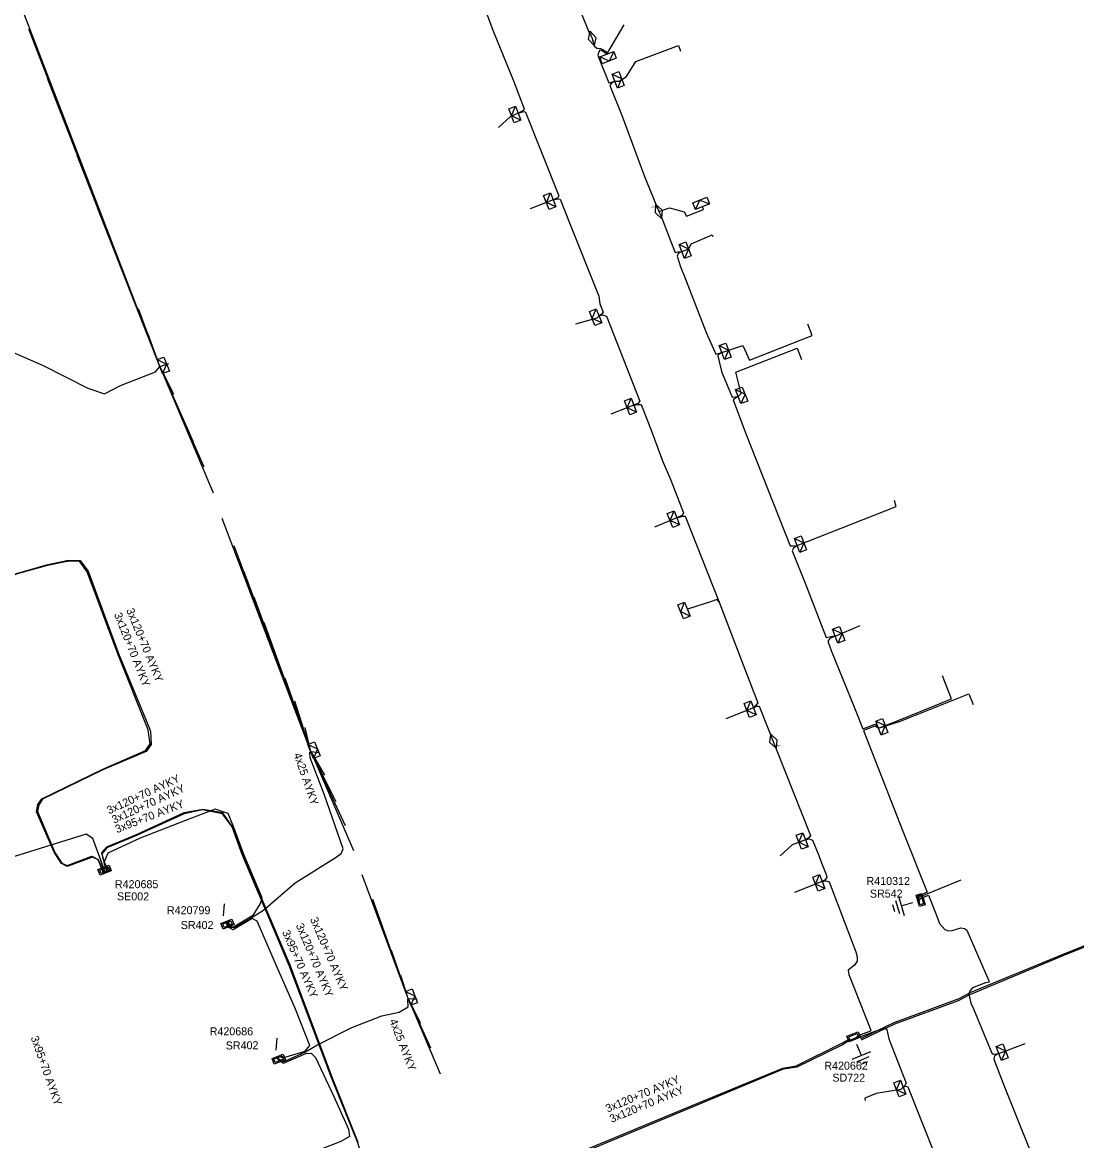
# Model space of a CAD drawing. Extents: x -540028 to -538776, y -1157064 to -1155670.
# Drawn here: x -539818.5 to -539686.8, y -1156318.7 to -1156179 of the extents above; entities that cross this region are included whole.
import ezdxf

# ---------------------------------------------------------------- set-up
doc = ezdxf.new("R2010")
doc.units = 0
for name, color, linetype in [('Vrstva 15', 7, 'Continuous'), ('Vrstva 19', 7, 'Continuous'), ('Vrstva 2', 7, 'Continuous'), ('Vrstva 28', 7, 'Continuous'), ('Vrstva 29', 7, 'Continuous'), ('Vrstva 30', 7, 'Continuous'), ('Vrstva 31', 7, 'Continuous'), ('Vrstva 5', 7, 'Continuous'), ('Vrstva 52', 7, 'Continuous'), ('Vrstva 59', 7, 'Continuous'), ('Vrstva 6', 7, 'Continuous')]:
    doc.layers.add(name, color=color, linetype=linetype)

# ---------------------------------------------------------------- blocks, each defined once
blk = doc.blocks.new('17')
at = {"layer": 'Vrstva 2'}
blk.add_lwpolyline([(-1.875, 0), (0, 0.9375), (1.875, 0), (0, -0.9375)], close=True, dxfattribs=at)
blk = doc.blocks.new('17.1')
at = {"layer": 'Vrstva 2'}
blk.add_lwpolyline([(-1.875, 0), (0, 0.9375), (1.875, 0), (0, -0.9375)], close=True, dxfattribs=at)
blk.add_text('T', height=0.75, dxfattribs=at).set_placement((-1.875, -1.35))
blk = doc.blocks.new('132')
at = {"layer": 'Vrstva 2'}
for points in [[(-1.5, 1.5), (1.5, 1.5), (1.5, 0), (-1.5, 0)], [(-1.1, 1.2), (1.1, 1.2), (1.1, 0.3), (-1.1, 0.3)]]:
    blk.add_lwpolyline(points, close=True, dxfattribs=at)
blk = doc.blocks.new('23')
at = {"layer": 'Vrstva 2'}
blk.add_lwpolyline([(1.875, -1.8), (-1.875, -1.8), (-1.875, 0), (1.875, 0)], close=True, dxfattribs=at)
blk.add_lwpolyline([(1.875, 0), (0, -1.8), (-1.875, 0)], dxfattribs=at)
blk = doc.blocks.new('11')
at = {"layer": 'Vrstva 2'}
for p, q in [((0, -4.3), (0, -1.3)), ((-2.5, -4.3), (2.5, -4.3)), ((-1.7, -5.3), (1.7, -5.3)), ((-0.9, -6.3), (0.9, -6.3))]:
    blk.add_line(p, q, dxfattribs=at)

msp = doc.modelspace()

# ---------------------------------------------------------------- linework, layer by layer
at = {"layer": 'Vrstva 5'}
for points in [[(-539754.47, -1156163.05), (-539754.32, -1156163.21), (-539753.53, -1156165.27), (-539752.45, -1156168.17), (-539750.8, -1156172.24), (-539750.34, -1156173.42), (-539748.88, -1156177.28), (-539747.67, -1156180.3), (-539747.55, -1156180.35), (-539747.29, -1156180.99)], [(-539761.06, -1156176.27), (-539759.68, -1156179.97), (-539757.13, -1156186.3), (-539755.77, -1156189.78), (-539755.86, -1156189.98), (-539756.54, -1156190.32), (-539755.83, -1156190.1), (-539755.61, -1156190.2), (-539751.46, -1156200.66), (-539751.58, -1156200.92), (-539752.17, -1156201.15), (-539751.55, -1156201.02), (-539751.27, -1156201.08), (-539750.11, -1156204.01), (-539746.47, -1156213.2), (-539746.33, -1156214.13), (-539745.92, -1156215.19), (-539746.07, -1156215.42), (-539746.43, -1156215.64), (-539746.04, -1156215.53), (-539745.49, -1156215.68), (-539741.31, -1156226.32), (-539741.6, -1156226.6), (-539742.09, -1156226.8), (-539741.55, -1156226.7), (-539741.16, -1156226.71), (-539739.78, -1156230.26), (-539738.5, -1156233.74), (-539737.46, -1156236.16), (-539735.86, -1156240.23), (-539736.01, -1156240.55), (-539736.72, -1156240.88), (-539735.96, -1156240.67), (-539735.67, -1156240.67), (-539731.41, -1156251.42), (-539728.62, -1156258.71), (-539726.57, -1156263.97), (-539726.82, -1156264.29), (-539727.14, -1156264.61), (-539726.79, -1156264.39), (-539726.41, -1156264.39), (-539720.01, -1156280.56), (-539720.23, -1156280.84), (-539720.64, -1156281.08), (-539720.18, -1156280.96), (-539719.76, -1156281.14), (-539718.97, -1156283.04), (-539718.73, -1156283.78), (-539718.04, -1156285.44), (-539717.95, -1156285.8), (-539718.17, -1156286.11), (-539718.56, -1156286.32), (-539718.1, -1156286.22), (-539717.69, -1156286.34), (-539714.34, -1156295.09), (-539714.16, -1156295.71), (-539714.19, -1156296.27), (-539714.51, -1156296.75), (-539715.3, -1156297.4), (-539715.23, -1156297.92), (-539712.47, -1156304.86), (-539712.51, -1156305.01), (-539714.11, -1156305.58), (-539714.39, -1156305.86), (-539714.35, -1156306)], [(-539747.29, -1156180.99), (-539747.03, -1156181.91), (-539746.7, -1156182.22), (-539746.25, -1156182.26), (-539746.04, -1156182.31), (-539745.58, -1156182.62), (-539745.45, -1156182.82), (-539745.47, -1156182.97)], [(-539745.47, -1156182.97), (-539745.61, -1156182.93), (-539745.72, -1156182.76), (-539746.12, -1156182.49), (-539746.32, -1156182.45), (-539746.44, -1156182.65), (-539746.58, -1156183.06), (-539746.49, -1156183.34), (-539745.22, -1156186.53), (-539745, -1156186.48), (-539744.46, -1156186.32), (-539744.92, -1156186.63), (-539745.07, -1156186.85), (-539743.55, -1156190.71), (-539740.75, -1156198.23), (-539738.96, -1156202.6), (-539738.7, -1156203.12), (-539737.44, -1156206.36), (-539736.9, -1156207.71), (-539736.58, -1156207.66), (-539736.1, -1156207.61), (-539736.53, -1156207.86), (-539736.65, -1156208.19), (-539736.26, -1156209.53), (-539735.83, -1156210.52), (-539733.05, -1156217.73), (-539731.84, -1156220.41), (-539731.56, -1156220.34), (-539731.1, -1156220.24), (-539731.53, -1156220.51), (-539731.59, -1156220.64), (-539731.11, -1156222.61), (-539729.78, -1156225.79), (-539729.43, -1156225.78), (-539729.03, -1156225.73), (-539729.36, -1156225.92), (-539729.69, -1156226.15), (-539728.12, -1156230.27), (-539722.53, -1156244.38), (-539722.23, -1156244.39), (-539721.69, -1156244.34), (-539722.12, -1156244.65), (-539722.28, -1156244.98), (-539720.58, -1156249.23), (-539718.04, -1156255.81), (-539717.28, -1156255.66), (-539716.91, -1156255.65), (-539717.61, -1156255.96), (-539717.85, -1156256.3), (-539717.41, -1156257.44), (-539714.53, -1156264.62), (-539713.49, -1156267.24), (-539711.94, -1156266.64), (-539711.53, -1156267.13), (-539711.97, -1156266.91), (-539713.4, -1156267.43), (-539708.49, -1156280), (-539705.43, -1156287.63), (-539706.58, -1156288.13), (-539706.7, -1156288.43)], [(-539826.32, -1156250.92), (-539819.2, -1156247.81), (-539815.3, -1156246.71), (-539812.7, -1156246.18), (-539811.25, -1156246.22), (-539810.27, -1156247.55), (-539806.46, -1156257.83), (-539802.57, -1156267.21), (-539802.46, -1156267.55), (-539802.39, -1156269.2), (-539802.99, -1156270.08), (-539808.42, -1156272.37), (-539815.96, -1156276.02), (-539816.4, -1156276.72), (-539816.57, -1156277.55), (-539814.42, -1156282.68), (-539813.56, -1156284.02), (-539812.88, -1156284.3), (-539809.79, -1156283.14), (-539808.99, -1156283.54), (-539808.71, -1156284.18), (-539808.23, -1156285.27)], [(-539808.35, -1156285.31), (-539808.75, -1156284.2), (-539809.01, -1156283.6), (-539809.72, -1156283.25), (-539812.86, -1156284.41), (-539813.59, -1156284.05), (-539814.52, -1156282.66), (-539816.7, -1156277.62), (-539816.54, -1156276.68), (-539816.05, -1156275.98), (-539808.42, -1156272.29), (-539803.07, -1156269.92), (-539802.5, -1156269.11), (-539802.7, -1156267.67), (-539802.75, -1156267.34), (-539806.55, -1156257.87), (-539810.37, -1156247.64), (-539811.34, -1156246.27), (-539812.66, -1156246.28), (-539815.33, -1156246.82), (-539819.13, -1156247.88), (-539826.28, -1156251.03)], [(-539792.97, -1156291.3), (-539792.59, -1156291.98), (-539792.37, -1156292.02), (-539791.94, -1156292.07), (-539790.05, -1156290.96), (-539789.75, -1156290.75), (-539788.35, -1156289.9), (-539784.4, -1156286.48), (-539779.28, -1156283.25), (-539778.63, -1156282.82), (-539778.4, -1156282.24), (-539780.75, -1156275.4), (-539782.53, -1156270.86), (-539782.56, -1156270.17), (-539782.45, -1156270.07)], [(-539713.64, -1156306.09), (-539709.48, -1156304.1), (-539701.5, -1156301.17), (-539700.17, -1156300.47), (-539688.46, -1156295.54), (-539660.98, -1156284.52), (-539655.52, -1156282.63), (-539647.32, -1156279.46), (-539637.77, -1156275.82)], [(-539776.5, -1156318.89), (-539779.74, -1156310.88), (-539785.02, -1156296.77), (-539790.94, -1156282.9), (-539792.22, -1156279.47), (-539793.43, -1156277.72), (-539795.89, -1156277.32), (-539798.28, -1156277.73), (-539804.24, -1156280.49), (-539807.96, -1156282.01), (-539808.6, -1156282.72), (-539808.19, -1156284.29), (-539807.93, -1156285.15)], [(-539779, -1156347.91), (-539779.95, -1156346.73), (-539779.73, -1156345.88), (-539778.61, -1156344.9), (-539775.24, -1156343.33), (-539770.56, -1156341.04), (-539769.48, -1156340.33), (-539769.63, -1156339.03), (-539771.64, -1156333.68), (-539773.7, -1156328.29), (-539775.54, -1156322.32), (-539776.58, -1156318.93), (-539779.82, -1156310.93), (-539785.14, -1156296.81), (-539791.02, -1156282.92), (-539792.28, -1156279.49), (-539793.49, -1156277.84), (-539795.98, -1156277.37), (-539798.25, -1156277.83), (-539804.23, -1156280.56), (-539807.94, -1156282.09), (-539808.56, -1156282.83), (-539808.18, -1156284.31), (-539807.82, -1156285.1)], [(-539792.85, -1156291.25), (-539792.48, -1156291.89), (-539792.11, -1156291.98), (-539789.61, -1156290.46), (-539788.71, -1156289.04), (-539788.52, -1156288.36), (-539790.8, -1156282.91), (-539792.1, -1156279.43), (-539792.75, -1156277.81), (-539794.39, -1156277.27), (-539798.1, -1156278.69), (-539803.74, -1156280.89), (-539807.78, -1156282.78), (-539808.24, -1156283.84), (-539807.7, -1156285.06)], [(-539713.7, -1156305.93), (-539709.54, -1156303.92), (-539701.45, -1156300.9), (-539700.08, -1156300.16), (-539688.52, -1156295.42), (-539661.09, -1156284.36), (-539655.55, -1156282.49), (-539647.32, -1156279.34), (-539647.14, -1156279.27), (-539646.88, -1156279.78)], [(-539808.1, -1156285.22), (-539809.67, -1156280.95), (-539810.49, -1156280.4), (-539819.47, -1156283.18), (-539829.52, -1156287.35), (-539831.83, -1156288.01), (-539835.74, -1156289.34), (-539852.03, -1156295.75), (-539867.05, -1156301.42), (-539893.47, -1156311.06), (-539905.35, -1156315.36), (-539906.2, -1156315.83), (-539906.45, -1156316.73), (-539906.39, -1156317.1)], [(-539706.55, -1156288.92), (-539706.28, -1156288.43), (-539705.28, -1156287.99), (-539704.31, -1156290.44), (-539703.89, -1156291.54), (-539703.24, -1156292.29), (-539702.77, -1156292.47), (-539702.29, -1156292.44), (-539701.24, -1156292.08), (-539700.76, -1156292.19), (-539700.49, -1156292.38), (-539697.72, -1156298.71), (-539697.69, -1156298.88), (-539698.15, -1156298.95), (-539699.76, -1156299.58), (-539700.08, -1156299.92), (-539700.23, -1156300.35), (-539699.98, -1156301.52), (-539699.63, -1156302.22), (-539697.35, -1156307.75), (-539697.13, -1156307.88), (-539696.47, -1156307.77), (-539697.02, -1156308.09), (-539697.12, -1156308.51), (-539695.93, -1156311.52), (-539690.98, -1156323.89)], [(-539786.41, -1156308.11), (-539785.95, -1156308.31), (-539783.14, -1156307.49), (-539782.54, -1156306.77), (-539784.44, -1156302.04), (-539786.58, -1156297.14), (-539789.15, -1156291.24), (-539789.76, -1156290.91), (-539792.15, -1156292.34), (-539792.68, -1156292.06), (-539793.09, -1156291.34)], [(-539786.58, -1156308.18), (-539786.44, -1156308.48), (-539785.78, -1156308.78), (-539783.08, -1156307.59), (-539781.7, -1156306.73), (-539777.3, -1156304.53), (-539773.58, -1156303.08), (-539771.41, -1156302.61), (-539770.27, -1156301.95), (-539770.32, -1156301.04), (-539770.27, -1156300.9)], [(-539714.18, -1156305.93), (-539714.19, -1156305.89), (-539714.05, -1156305.77), (-539711.92, -1156305.02), (-539710.74, -1156304.57), (-539710.49, -1156304.79), (-539710.22, -1156305.95), (-539708.05, -1156311.49), (-539708.21, -1156311.78), (-539708.42, -1156312), (-539708.14, -1156311.87), (-539707.85, -1156311.96), (-539702.63, -1156325.04)], [(-539779.43, -1156348.07), (-539780.03, -1156346.76), (-539779.79, -1156345.7), (-539778.81, -1156344.68), (-539775.19, -1156343.16), (-539770.61, -1156340.97), (-539769.67, -1156340.19), (-539769.72, -1156339.08), (-539771.9, -1156333.83), (-539772.63, -1156331.81), (-539772.46, -1156331.12), (-539768.16, -1156328.91), (-539760.28, -1156325.42), (-539754.68, -1156322.8), (-539751.87, -1156321.38), (-539734.78, -1156314.29), (-539723.45, -1156309.64), (-539721.79, -1156309.32), (-539716.19, -1156306.53), (-539715.16, -1156306), (-539714.89, -1156306.22)], [(-539779.1, -1156347.94), (-539779.99, -1156346.75), (-539779.78, -1156345.83), (-539778.71, -1156344.76), (-539775.28, -1156343.26), (-539770.58, -1156340.98), (-539769.62, -1156340.26), (-539769.67, -1156339.06), (-539771.71, -1156333.71), (-539772.29, -1156331.91), (-539772.31, -1156331.17), (-539768.05, -1156329.1), (-539760.25, -1156325.54), (-539754.53, -1156322.92), (-539751.76, -1156321.51), (-539734.73, -1156314.46), (-539723.4, -1156309.72), (-539721.66, -1156309.44), (-539716.13, -1156306.73), (-539715.24, -1156306.18), (-539715.07, -1156306.3)], [(-539786.69, -1156308.23), (-539786.54, -1156308.51), (-539785.86, -1156308.98), (-539783.04, -1156307.79), (-539782.4, -1156307.75), (-539781.84, -1156308.29), (-539779.58, -1156313.15), (-539777.72, -1156317.26), (-539777.6, -1156318.14), (-539778.7, -1156318.77), (-539784.02, -1156320.88), (-539795.1, -1156324.88), (-539804.64, -1156328.28), (-539811.88, -1156330.75), (-539813.44, -1156331.06), (-539814.03, -1156330.55), (-539816.6, -1156323.5), (-539818.29, -1156320), (-539820, -1156320.5)]]:
    msp.add_lwpolyline(points, dxfattribs=at)
at = {"layer": 'Vrstva 52'}
for points in [[(-539744.46, -1156186.32), (-539743.91, -1156186.32), (-539742.98, -1156185.76), (-539741.82, -1156183.89), (-539736.5, -1156181.87), (-539736.23, -1156182.56)], [(-539756.54, -1156190.32), (-539757.55, -1156190.79), (-539758.97, -1156192.12)], [(-539752.17, -1156201.15), (-539755.03, -1156202.28)], [(-539738.96, -1156202.6), (-539737.62, -1156202.16), (-539735.78, -1156202.63), (-539735.52, -1156203.2), (-539733.37, -1156202.36), (-539733.51, -1156202.01)], [(-539736.1, -1156207.61), (-539735.21, -1156207.27), (-539734.9, -1156206.65), (-539732.28, -1156205.52), (-539732.21, -1156205.72)], [(-539828.61, -1156212.03), (-539826.96, -1156211.96), (-539826.13, -1156212.07), (-539825.59, -1156212.71), (-539823.69, -1156217.36), (-539822.37, -1156218.83), (-539820.76, -1156219.73), (-539815.89, -1156221.84), (-539810.28, -1156224.66), (-539808.21, -1156225.38), (-539806.21, -1156224.36), (-539801.84, -1156222.64), (-539801.29, -1156221.99)], [(-539746.43, -1156215.64), (-539746.69, -1156215.94), (-539749.36, -1156216.68)], [(-539731.1, -1156220.24), (-539728.48, -1156219.35), (-539727.65, -1156221.16), (-539719.78, -1156218.11), (-539720.33, -1156216.67)], [(-539729.03, -1156225.73), (-539728.68, -1156225.33), (-539729.35, -1156222.69), (-539721.69, -1156219.67), (-539721.13, -1156221.11)], [(-539742.09, -1156226.8), (-539744.94, -1156227.93)], [(-539721.69, -1156244.34), (-539709.32, -1156239.45), (-539709.53, -1156238.7)], [(-539736.72, -1156240.88), (-539739.49, -1156242.03)], [(-539731.41, -1156251.42), (-539731.65, -1156251.09), (-539732.51, -1156251.36), (-539735.38, -1156252.28)], [(-539716.91, -1156255.65), (-539713.8, -1156254.32)], [(-539711.53, -1156267.13), (-539708.83, -1156266.09), (-539702.4, -1156263.5), (-539703.51, -1156260.6)], [(-539711.53, -1156267.13), (-539708.77, -1156266.27), (-539700.21, -1156262.84), (-539699.67, -1156264.19)], [(-539727.14, -1156264.61), (-539730.57, -1156265.97)], [(-539720.64, -1156281.08), (-539722.3, -1156281.72), (-539723.79, -1156283.08)], [(-539718.56, -1156286.32), (-539722.01, -1156287.67)], [(-539706.62, -1156288.67), (-539706.43, -1156288.28), (-539705.36, -1156287.81), (-539701.18, -1156286.11)], [(-539696.47, -1156307.77), (-539693.2, -1156306.53)], [(-539708.42, -1156312), (-539708.71, -1156312.27), (-539711.81, -1156312.77), (-539713.24, -1156313.36), (-539713.19, -1156313.66)]]:
    msp.add_lwpolyline(points, dxfattribs=at)
at = {"layer": 'Vrstva 59'}
for points in [[(-539801.29, -1156221.99), (-539819.63, -1156174.34)], [(-539745.47, -1156182.97), (-539743.29, -1156179.3)], [(-539801.29, -1156221.99), (-539817.68, -1156179.85)], [(-539801.29, -1156221.99), (-539816.56, -1156182.74)], [(-539801.29, -1156221.99), (-539815.34, -1156186.01)], [(-539801.29, -1156221.99), (-539813.94, -1156189.28)], [(-539801.29, -1156221.99), (-539812.82, -1156192.36)], [(-539801.29, -1156221.99), (-539811.61, -1156195.63)], [(-539801.29, -1156221.99), (-539810.3, -1156198.89)], [(-539801.29, -1156221.99), (-539809.09, -1156202.16)], [(-539801.29, -1156221.99), (-539807.79, -1156205.15)], [(-539801.29, -1156221.99), (-539806.57, -1156208.51)], [(-539801.29, -1156221.99), (-539805.36, -1156211.59)], [(-539801.29, -1156221.99), (-539803.96, -1156214.76)], [(-539801.29, -1156221.99), (-539802.75, -1156217.94)], [(-539801.29, -1156221.99), (-539800.16, -1156221.61)], [(-539801.29, -1156221.99), (-539798.42, -1156228.49)], [(-539801.29, -1156221.99), (-539799.58, -1156225.41)], [(-539801.29, -1156221.99), (-539797.13, -1156231.38)], [(-539801.29, -1156221.99), (-539795.82, -1156234.49)], [(-539801.29, -1156221.99), (-539794.64, -1156237.74)], [(-539782.45, -1156270.07), (-539793.5, -1156240.94)], [(-539782.45, -1156270.07), (-539792.03, -1156244.36)], [(-539782.45, -1156270.07), (-539790.75, -1156247.62)], [(-539782.45, -1156270.07), (-539789.51, -1156250.79)], [(-539782.45, -1156270.07), (-539788.26, -1156253.93)], [(-539782.45, -1156270.07), (-539787.05, -1156257.4)], [(-539782.45, -1156270.07), (-539785.62, -1156260.91)], [(-539782.45, -1156270.07), (-539784.44, -1156263.77)], [(-539782.45, -1156270.07), (-539783.13, -1156267.06)], [(-539782.45, -1156270.07), (-539781.34, -1156270.17)], [(-539782.45, -1156270.07), (-539780.74, -1156273.02)], [(-539782.45, -1156270.07), (-539779.33, -1156276.33)], [(-539782.45, -1156270.07), (-539778.14, -1156279.3)], [(-539782.45, -1156270.07), (-539777.12, -1156282.45)], [(-539770.27, -1156300.9), (-539776.04, -1156285.46)], [(-539793.35, -1156290.59), (-539793.21, -1156289.08)], [(-539770.27, -1156300.9), (-539774.7, -1156288.57)], [(-539770.27, -1156300.9), (-539773.58, -1156291.79)], [(-539770.27, -1156300.9), (-539772.34, -1156294.91)], [(-539770.27, -1156300.9), (-539771.17, -1156298.04)], [(-539770.27, -1156300.9), (-539768.73, -1156304.02)], [(-539770.27, -1156300.9), (-539767.48, -1156307.1)], [(-539770.27, -1156300.9), (-539766.27, -1156310.31)], [(-539770.27, -1156300.9), (-539769.16, -1156301)], [(-539786.76, -1156307.39), (-539786.62, -1156305.89)]]:
    msp.add_lwpolyline(points, dxfattribs=at)

# ---------------------------------------------------------------- block references
at = {"layer": 'Vrstva 15', "yscale": 0.5}
for p, xscale, rotation in [((-539706.61, -1156288.72), 0.5000000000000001, -73.35790830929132), ((-539714.47, -1156306.05), 0.5, 22.670749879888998)]:
    msp.add_blockref('11', p, dxfattribs=dict(at, xscale=xscale, rotation=rotation))
at = {"layer": 'Vrstva 19'}
for name, p, xscale, yscale, rotation in [('17', (-539747.29, -1156180.99), 0.5, 0.5, -74.21924665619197), ('17.1', (-539738.96, -1156202.6), 0.5000000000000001, 0.4999999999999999, -67.72895275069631), ('17.1', (-539724.64, -1156268.76), 0.5000000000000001, 0.5, 110.9158166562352)]:
    msp.add_blockref(name, p, dxfattribs=dict(at, xscale=xscale, yscale=yscale, rotation=rotation))
at = {"layer": 'Vrstva 28'}
for p, xscale, yscale, rotation in [((-539808.06, -1156285.23), 0.49999999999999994, 0.5000000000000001, 21.56201391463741), ((-539706.61, -1156288.72), 0.5, 0.5, -73.35790824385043), ((-539792.98, -1156291.27), 0.5, 0.5, -158.33814169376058), ((-539714.47, -1156306.05), 0.5000000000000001, 0.4999999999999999, 22.330258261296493), ((-539786.58, -1156308.15), 0.5, 0.5, -158.35915271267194)]:
    msp.add_blockref('132', p, dxfattribs=dict(at, xscale=xscale, yscale=yscale, rotation=rotation))
at = {"layer": 'Vrstva 31'}
for p, xscale, yscale, rotation in [((-539745.47, -1156182.97), 0.5, 0.49999999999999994, 21.092339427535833), ((-539744.46, -1156186.32), 0.5, 0.5, 111.03751109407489), ((-539756.54, -1156190.32), 0.5, 0.5, -68.96248895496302), ((-539752.17, -1156201.15), 0.5, 0.5, -68.96248895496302), ((-539733.51, -1156202.01), 0.49999999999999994, 0.5000000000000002, -158.61777787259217), ((-539736.1, -1156207.61), 0.49999999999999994, 0.5000000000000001, 111.037511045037), ((-539746.43, -1156215.64), 0.5, 0.5, -68.96248895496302), ((-539731.1, -1156220.24), 0.5, 0.5, 111.03751109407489), ((-539801.29, -1156221.99), 0.5, 0.5, 111.37741948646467), ((-539729.03, -1156225.73), 0.5, 0.49999999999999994, 111.03751115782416), ((-539742.09, -1156226.8), 0.49999999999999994, 0.5000000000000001, -68.96248889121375), ((-539736.72, -1156240.88), 0.49999999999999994, 0.5000000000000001, -68.96248889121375), ((-539721.69, -1156244.34), 0.5, 0.49999999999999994, 111.03751115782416), ((-539735.38, -1156252.28), 0.5, 0.49999999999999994, -67.94356664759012), ((-539716.91, -1156255.65), 0.5, 0.5, 110.8544583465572), ((-539727.14, -1156264.61), 0.5, 0.5, -68.96248895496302), ((-539711.53, -1156267.13), 0.49999999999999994, 0.5000000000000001, 111.037511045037), ((-539782.45, -1156270.07), 0.5, 0.49999999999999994, 111.55166663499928), ((-539720.64, -1156281.08), 0.5, 0.5, -68.96248895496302), ((-539718.56, -1156286.32), 0.5, 0.5, -68.96248895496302), ((-539770.27, -1156300.9), 0.5, 0.49999999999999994, 111.55166663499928), ((-539696.47, -1156307.77), 0.5, 0.5, 111.03751109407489), ((-539708.42, -1156312), 0.49999999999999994, 0.5000000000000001, -68.96248890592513)]:
    msp.add_blockref('23', p, dxfattribs=dict(at, xscale=xscale, yscale=yscale, rotation=rotation))

# ---------------------------------------------------------------- texts
at = {"layer": 'Vrstva 29'}
for s, p in [('R420685', (-539806.91, -1156287.14)), ('R420799', (-539800.41, -1156290.39)), ('R420686', (-539795.07, -1156305.52))]:
    msp.add_text(s, height=1, dxfattribs=at).set_placement(p)
for s, rotation, p in [('R410312', 0.069, (-539713.01, -1156286.74)), ('R420662', 0.026, (-539718.28, -1156309.81))]:
    msp.add_text(s, height=1, rotation=rotation, dxfattribs=at).set_placement(p)
at = {"layer": 'Vrstva 30'}
for s, rotation, p in [('SE002', 359.643, (-539806.65, -1156288.65)), ('SR542', 0.214, (-539712.59, -1156288.32)), ('SR402', 0.071, (-539798.68, -1156292.24)), ('SR402', 0.529, (-539793.06, -1156307.29)), ('SD722', 359.728, (-539717.28, -1156311.3))]:
    msp.add_text(s, height=1, rotation=rotation, dxfattribs=at).set_placement(p)
at = {"layer": 'Vrstva 6'}
for s, rotation, p in [('3x120+70 AYKY', 291.811, (-539807.04, -1156252.94)), ('3x120+70 AYKY', 292.493, (-539805.52, -1156252.4)), ('4x25 AYKY', 288.983, (-539784.6, -1156270.42)), ('3x120+70 AYKY', 24.858, (-539807.64, -1156277.93)), ('3x120+70 AYKY', 24.5, (-539807.03, -1156279.1)), ('3x95+70 AYKY', 21.306, (-539806.65, -1156280.28)), ('3x120+70 AYKY', 293.145, (-539782.55, -1156291.01)), ('3x95+70 AYKY', 293.574, (-539786.05, -1156292.62)), ('3x120+70 AYKY', 292.914, (-539784.33, -1156291.77)), ('4x25 AYKY', 291.329, (-539772.64, -1156303.69)), ('3x95+70 AYKY', 289.401, (-539817.45, -1156305.79)), ('3x120+70 AYKY', 22.544, (-539745.36, -1156315.18)), ('3x120+70 AYKY', 22.489, (-539744.86, -1156316.47))]:
    msp.add_text(s, height=1, rotation=rotation, dxfattribs=at).set_placement(p)

doc.saveas('drawing.dxf')
